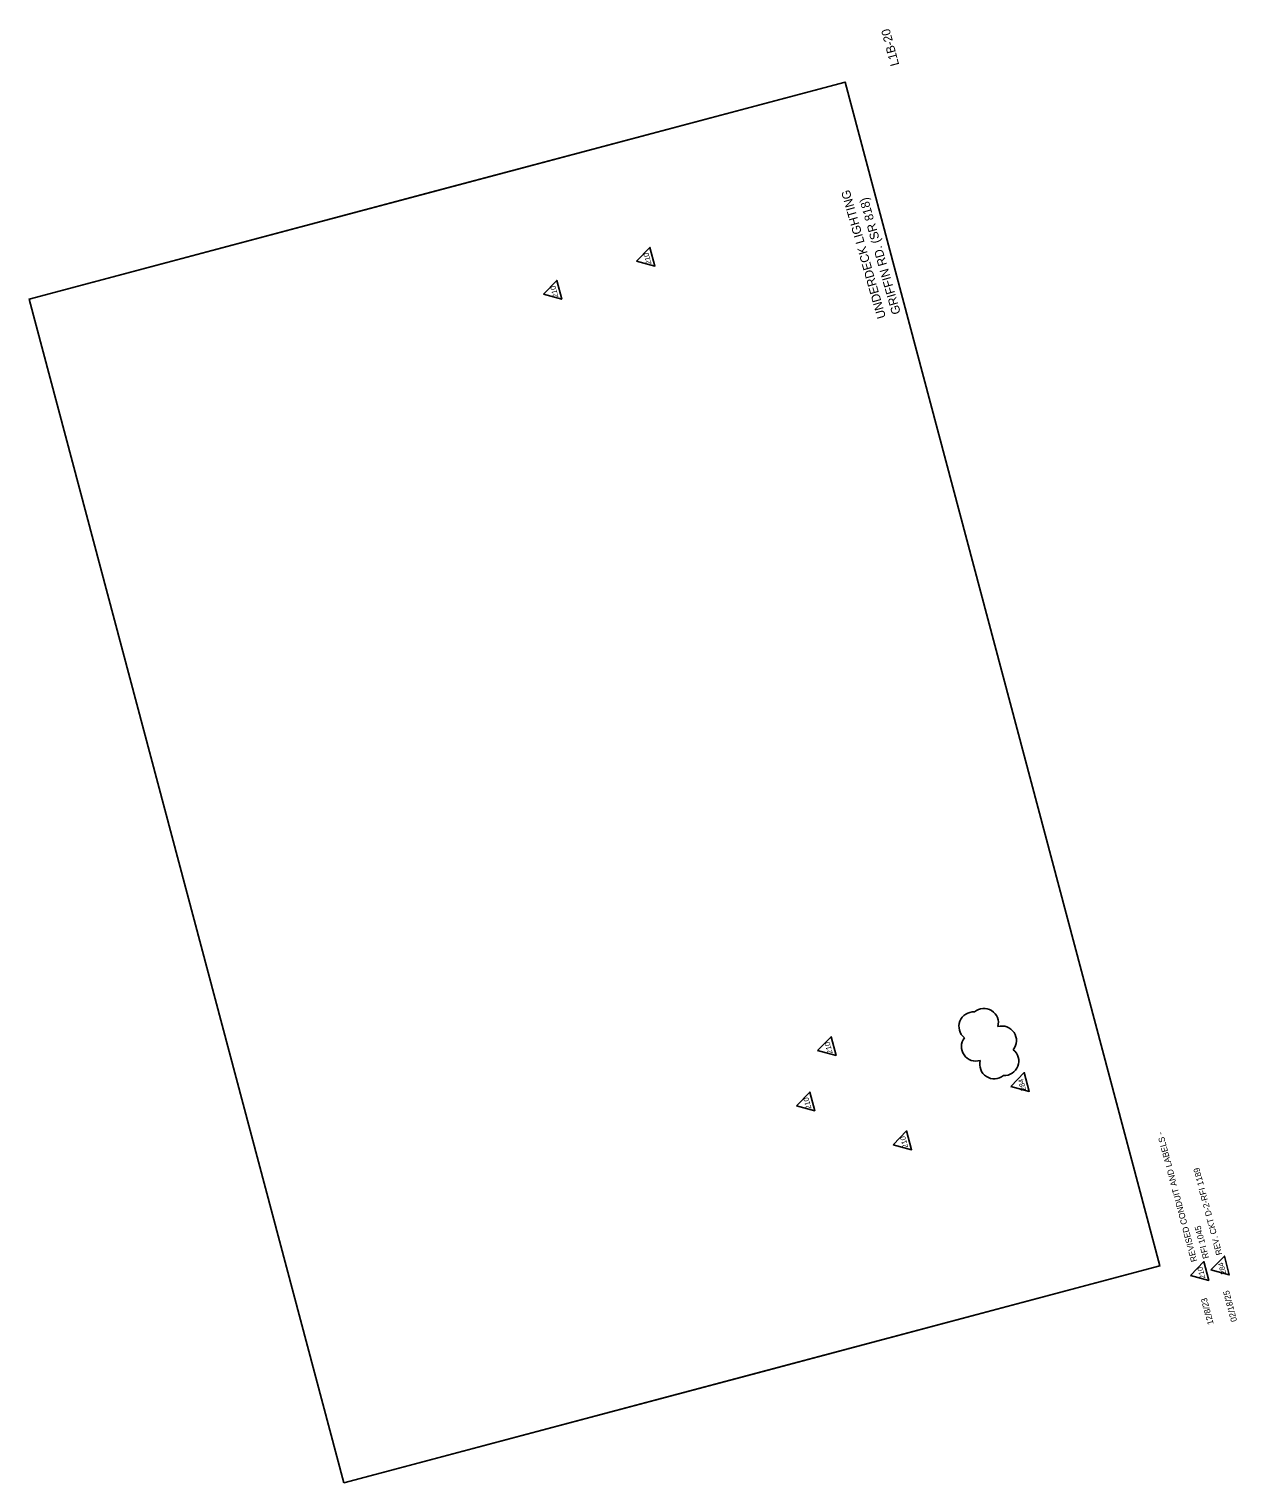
# Model space of a CAD drawing. Extents: x 930425 to 930974, y 629099 to 629760.
import ezdxf

# ---------------------------------------------------------------- set-up
doc = ezdxf.new("R2010")
doc.units = 0
for name, color, linetype in [('ActivePointCell_dp', 7, 'Continuous'), ('Cloud_dp', 7, 'Continuous'), ('MatchLines_dp', 7, 'Continuous'), ('TextMinor', 7, 'Continuous'), ('TextShtNo', 7, 'Continuous'), ('TextTitle', 7, 'Continuous')]:
    doc.layers.add(name, color=color, linetype=linetype)

msp = doc.modelspace()

# ---------------------------------------------------------------- linework, layer by layer
at = {"layer": 'ActivePointCell_dp'}
msp.add_lwpolyline([(930567.78, 629098.98), (930424.61, 629637.39), (930795.69, 629736.06), (930938.85, 629197.65)], close=True, dxfattribs=at)
at = {"layer": 'Cloud_dp'}
for points in [[(930700.81, 629654.61), (930709.19, 629652.38), (930706.92, 629660.91)], [(930658.48, 629639.55), (930666.86, 629637.32), (930664.59, 629645.85)], [(930783.18, 629295.64), (930791.56, 629293.4), (930789.29, 629301.93)], [(930871.04, 629279.27), (930879.41, 629277.04), (930877.15, 629285.57)], [(930773.53, 629270.44), (930781.91, 629268.21), (930779.64, 629276.74)], [(930817.52, 629252.77), (930825.89, 629250.54), (930823.63, 629259.07)], [(930962.03, 629195.82), (930970.41, 629193.59), (930968.14, 629202.12)], [(930952.7, 629193.34), (930961.08, 629191.11), (930958.81, 629199.64)]]:
    msp.add_lwpolyline(points, close=True, dxfattribs=at)
for centre, radius, start, end in [((930858.79, 629308.17), 6.6, 345.49678, 130.49678), ((930854.07, 629306.59), 6.61, 86.25677, 231.25677), ((930855.17, 629297.42), 6.6, 142.52492, 287.52492), ((930867, 629300.17), 6.61, 321.06991, 106.06991), ((930868.07, 629290.83), 6.6, 266.85703, 51.85703), ((930863.52, 629289.34), 6.6, 164.36355, 309.36355)]:
    msp.add_arc(centre, radius, start, end, dxfattribs=at)
at = {"layer": 'MatchLines_dp'}
for points in [[(930795.68, 629736.06), (930610.15, 629686.72), (930424.61, 629637.39)], [(930938.85, 629197.65), (930753.31, 629148.32), (930567.78, 629098.98)]]:
    msp.add_lwpolyline(points, dxfattribs=at)

# ---------------------------------------------------------------- texts
at = {"layer": 'Cloud_dp'}
for s, p in [('210', (930707.67, 629653.4)), ('210', (930665.34, 629638.34)), ('210', (930790.04, 629294.43)), ('284', (930878.02, 629277.6)), ('210', (930780.39, 629269.23)), ('210', (930824.38, 629251.56)), ('210', (930959.56, 629192.14)), ('284', (930969.01, 629194.15))]:
    msp.add_text(s, height=2.399, rotation=104.89046, dxfattribs=at).set_placement(p)
at = {"layer": 'TextMinor'}
for s, p in [('REVISED CONDUIT AND LABELS - ', (930955.82, 629199.93)), ('REV. CKT D-2-RFI 1189', (930967.24, 629202.97)), ('RFI 1045', (930961.23, 629201.37)), ('12/8/23', (930963.32, 629171.33)), ('02/18/25', (930973.97, 629172.67))]:
    msp.add_text(s, height=2.8, rotation=104.89045, dxfattribs=at).set_placement(p)
at = {"layer": 'TextShtNo'}
msp.add_text('L1B-20', height=4, rotation=104.89045, dxfattribs=at).set_placement((930820.31, 629743.97))
at = {"layer": 'TextTitle'}
for s, p in [('UNDERDECK LIGHTING', (930814.3, 629629.13)), ('GRIFFIN RD. (SR 818)', (930821.03, 629631.05))]:
    msp.add_text(s, height=4, rotation=105.93321, dxfattribs=at).set_placement(p)

doc.saveas('drawing.dxf')
